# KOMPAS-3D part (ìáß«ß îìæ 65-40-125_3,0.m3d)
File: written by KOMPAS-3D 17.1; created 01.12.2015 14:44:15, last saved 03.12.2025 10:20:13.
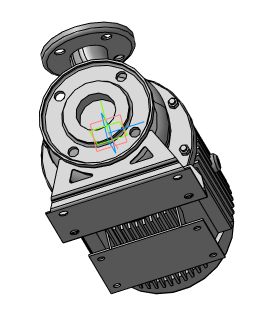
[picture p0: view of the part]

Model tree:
1. Операция без истории:3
